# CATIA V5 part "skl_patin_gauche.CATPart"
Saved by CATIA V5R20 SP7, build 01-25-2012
Part number: skl_patin_gauche
Publications: "Axe_pivot_patin_gauche_bras_gauche", "Plan.1"
Bounding box of the stored display mesh (mm): x -524.226 to -350, y 0 to 0, z 0 to 20
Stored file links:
  U:\IAO\thinkmotion catia2\skl_patin_gauche.CATPart
  U:\IAO\thinkmotion catia2\skl_862_adubourgno.CATProduct
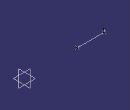
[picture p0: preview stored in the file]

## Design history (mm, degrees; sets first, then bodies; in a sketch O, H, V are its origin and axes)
Set1
  Point1 "I": linked copy from another document
  Point2 "N": linked copy from another document
  Plane1: linked copy from another document
Set2
  Line1: type PtPt, FirstPoint Point1, SecondPoint Point2
  Line2 "Axe_pivot_patin_gauche_bras_gauche": type Normal, RefPoint Point1, RefSkin Plane1, Start 0, End 20
Body1 (main body)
